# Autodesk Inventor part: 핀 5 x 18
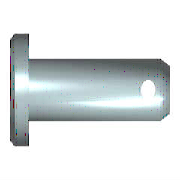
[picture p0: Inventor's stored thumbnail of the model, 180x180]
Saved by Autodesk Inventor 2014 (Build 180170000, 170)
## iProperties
Created: 2012-02
Part Number: 핀 5 x 18
Material: 강철
Description: 머리가 있는 클레비스 핀
Document SubType Name: Modeling
Standard: ISO 2341
Designer: test
Standard Revision: Second edition 1986-11-01
Standards Organization: ISO
Language: ko-KR
Size Designation: B - 5 x 18
Categories: <MemberInstance><Categories><Category DisplayName="조임쇠" InternalName="e4da775c-781d-43d5-af7c-5136215cf5a6" Mnemonic="FSTN"><Category DisplayName="핀" InternalNa
Density: 7.85 g/cm^3
Appearance: 강철
IsCustomPart: 1
Author: test
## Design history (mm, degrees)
sketch "스케치1"
  geometry: L1 (-1.6, 0)-(-1.6, 4); L2 (-1.6, 4)-(0, 4); L3 (0, 4)-(0, 2.5); L4 (0, 2.5)-(18, 2.5); L5 (18, 2.5)-(18, 0); L6 (-1.6, 0)-(18, 0); L7 (-4, 0)-(17, 0) reference; L8 (0, -0.98)-(0, 3.08) reference; C1 r 0.6 at (15.1, 0)
  constraints: 12 end point, 3 parallel, 2 collinear, 2 perpendicular, 1 centre point, 1 point on line, 1 vertical
  dimensions: "d0" = 5 diameter of L4 L6 (= NND); "d1" = 8 diameter of L2 L6 (= KOD); "d2" = 1.6 distance of L1.end L2.end (= KOH); "d3" = 18 distance of L3.end L4.end (= NLG); "d5" = 2.9 distance from line of L5 C1.centre (= DIST); "d6" = 1.2 diameter of C1 (= BOR)
revolve "본체" stored, may be unused: angle "d4" = 90 deg
extrude "구멍" cut sketch "스케치1" stored distance "d7" = 5 (= NND); taper "d8" = 0 deg
workaxis "Work Axis1"
workplane "Work Plane1"
node "작업 평면4"
body "Solid1"
chamfer "모따기1" distance "d9" = 1 (= PHH2); stored, may be unused: angle "d10" = 45 deg (= FAWI2), second distance "d16" = 1 (= PHH2)
chamfer "모따기2" distance "d11" = 2 (= PHH1); stored, may be unused: angle "d12" = 30 deg (= FAWI1), second distance "d17" = 2 (= PHH1)
other parameters: "PHH1" = 2 [user parameter; used in 2 equation terms], "PHH2" = 1 [user parameter; used in 2 equation terms], "KOD" = 8 [user parameter; used in 1 equation term], "KOH" = 1.6 [user parameter; used in 1 equation term], "NND" = 5 [user parameter; used in 2 equation terms], "FAWI1" = 30 deg [user parameter; used in 1 equation term], "FAWI2" = 45 deg [user parameter; used in 1 equation term], "DIST" = 2.9 [user parameter; used in 1 equation term], "BOR" = 1.2 [user parameter; used in 1 equation term], "NLG" = 18 [user parameter; used in 1 equation term], "d13" = 0, "d14" = 0, "d27" = 0, "d28" = 0, "d29" = 0, "d30" = 0, "d31" = 0
